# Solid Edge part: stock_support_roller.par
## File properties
Title: Stock support roller
Author: Abhinav Rai
Template: Normal.par
Last saved by: CADCIM
Revision: 11
Application: Solid Edge
Material: aluminum
Density: 0 kg/mm^3
Accuracy: 0.99
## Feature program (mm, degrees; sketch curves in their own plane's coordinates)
sketch for "unnamed RevolvedProtrusion 1" plane through (0, 0, 0) normal (0, -1, 0) x-axis (1, 0, 0)
  line (60, 0) -> (60, 24.638)
  line (60, 24.638) -> (15.55, 24.638)
  line (15.55, 24.638) -> (15.55, 92.075)
  line (15.55, 92.075) -> (-2.2388, 92.075)
  line (-2.2388, 92.075) -> (-111.45, 29.0219)
  line (-220.6612, 92.075) -> (-111.45, 29.0219)
  line (-238.45, 92.075) -> (-220.6612, 92.075)
  line (-238.45, 24.638) -> (-238.45, 92.075)
  line (-282.9, 24.638) -> (-238.45, 24.638)
  line (-282.9, 0) -> (-282.9, 24.638)
revolve "unnamed RevolvedProtrusion 1" add full turn 360 deg about sketch line (-282.9, 0) -> (60, 0)
chamfer "unnamed Chamfer 1"
fillet "Round_1" radius 1.5748
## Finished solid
Body 1: solid body, 14 faces, 13 edges, 0 vertices.
  Faces by surface: cone 4, cylinder 4, plane 4, torus 2
  Edges by curve: circle 13
Bounding box of the edges (mm; curved faces can reach further): 342.900 x 184.150 x 184.150, from (-282.9, -92.075, -92.075) to (60, 92.075, 92.075).
Cylindrical faces by radius (mm): R24.638 x2, R92.075 x2
Conical faces (half-angle, radius in mm at the cone's reference point): 30 deg R29.0219 x1, 30 deg R92.075 x1, 45 deg R23.0632 x1, 45 deg R24.638 x1
Toroidal faces (ring radius, tube radius in mm): R26.2128 r1.5748 x2
Planar faces by outward normal: +x 2, -x 2
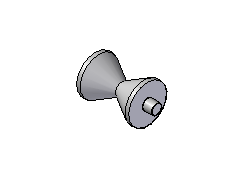
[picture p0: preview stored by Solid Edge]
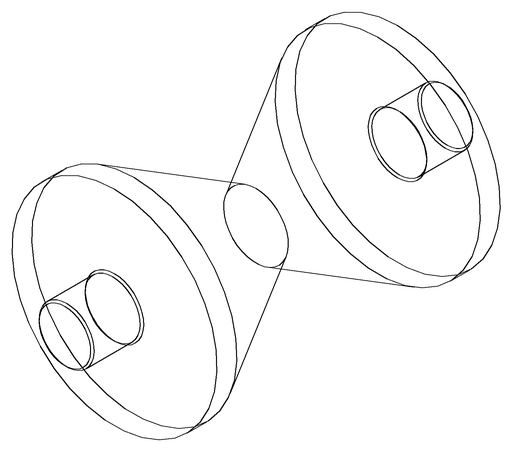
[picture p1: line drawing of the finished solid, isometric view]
